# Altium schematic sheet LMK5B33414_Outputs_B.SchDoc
size C; Date: Not shown in title block; ApprovedBy: Not shown in title block; CheckedBy: Not shown in title block; Author: Not shown in title block; CompanyName: Not shown in title block; Engineer: Not shown in title block; Organization: Not shown in title block; Address1: Not shown in title block; Address2: Not shown in title block; Address3: Not shown in title block; Address4: Not shown in title block; DocumentNumber: 2; Revision: Use project parameter SCH_Rev; SheetNumber: 2; SheetTotal: 3; PageSetup: Record=PageOptions¦CenterHorizontal=True¦CenterVertical=True¦PrintScale=1.00¦XCorrection=1.00¦YCorrection=1.00¦PrintKind=0¦BorderSize=5000000¦LeftOffset=0¦BottomOffset=0¦Orientation=2¦PaperLength=1000¦PaperWidth=1000¦Scale=100¦PaperSource=15¦PrintQuality=600¦MediaType=1¦DitherType=10¦PaperKind=Letter¦PrintScaleMode=1
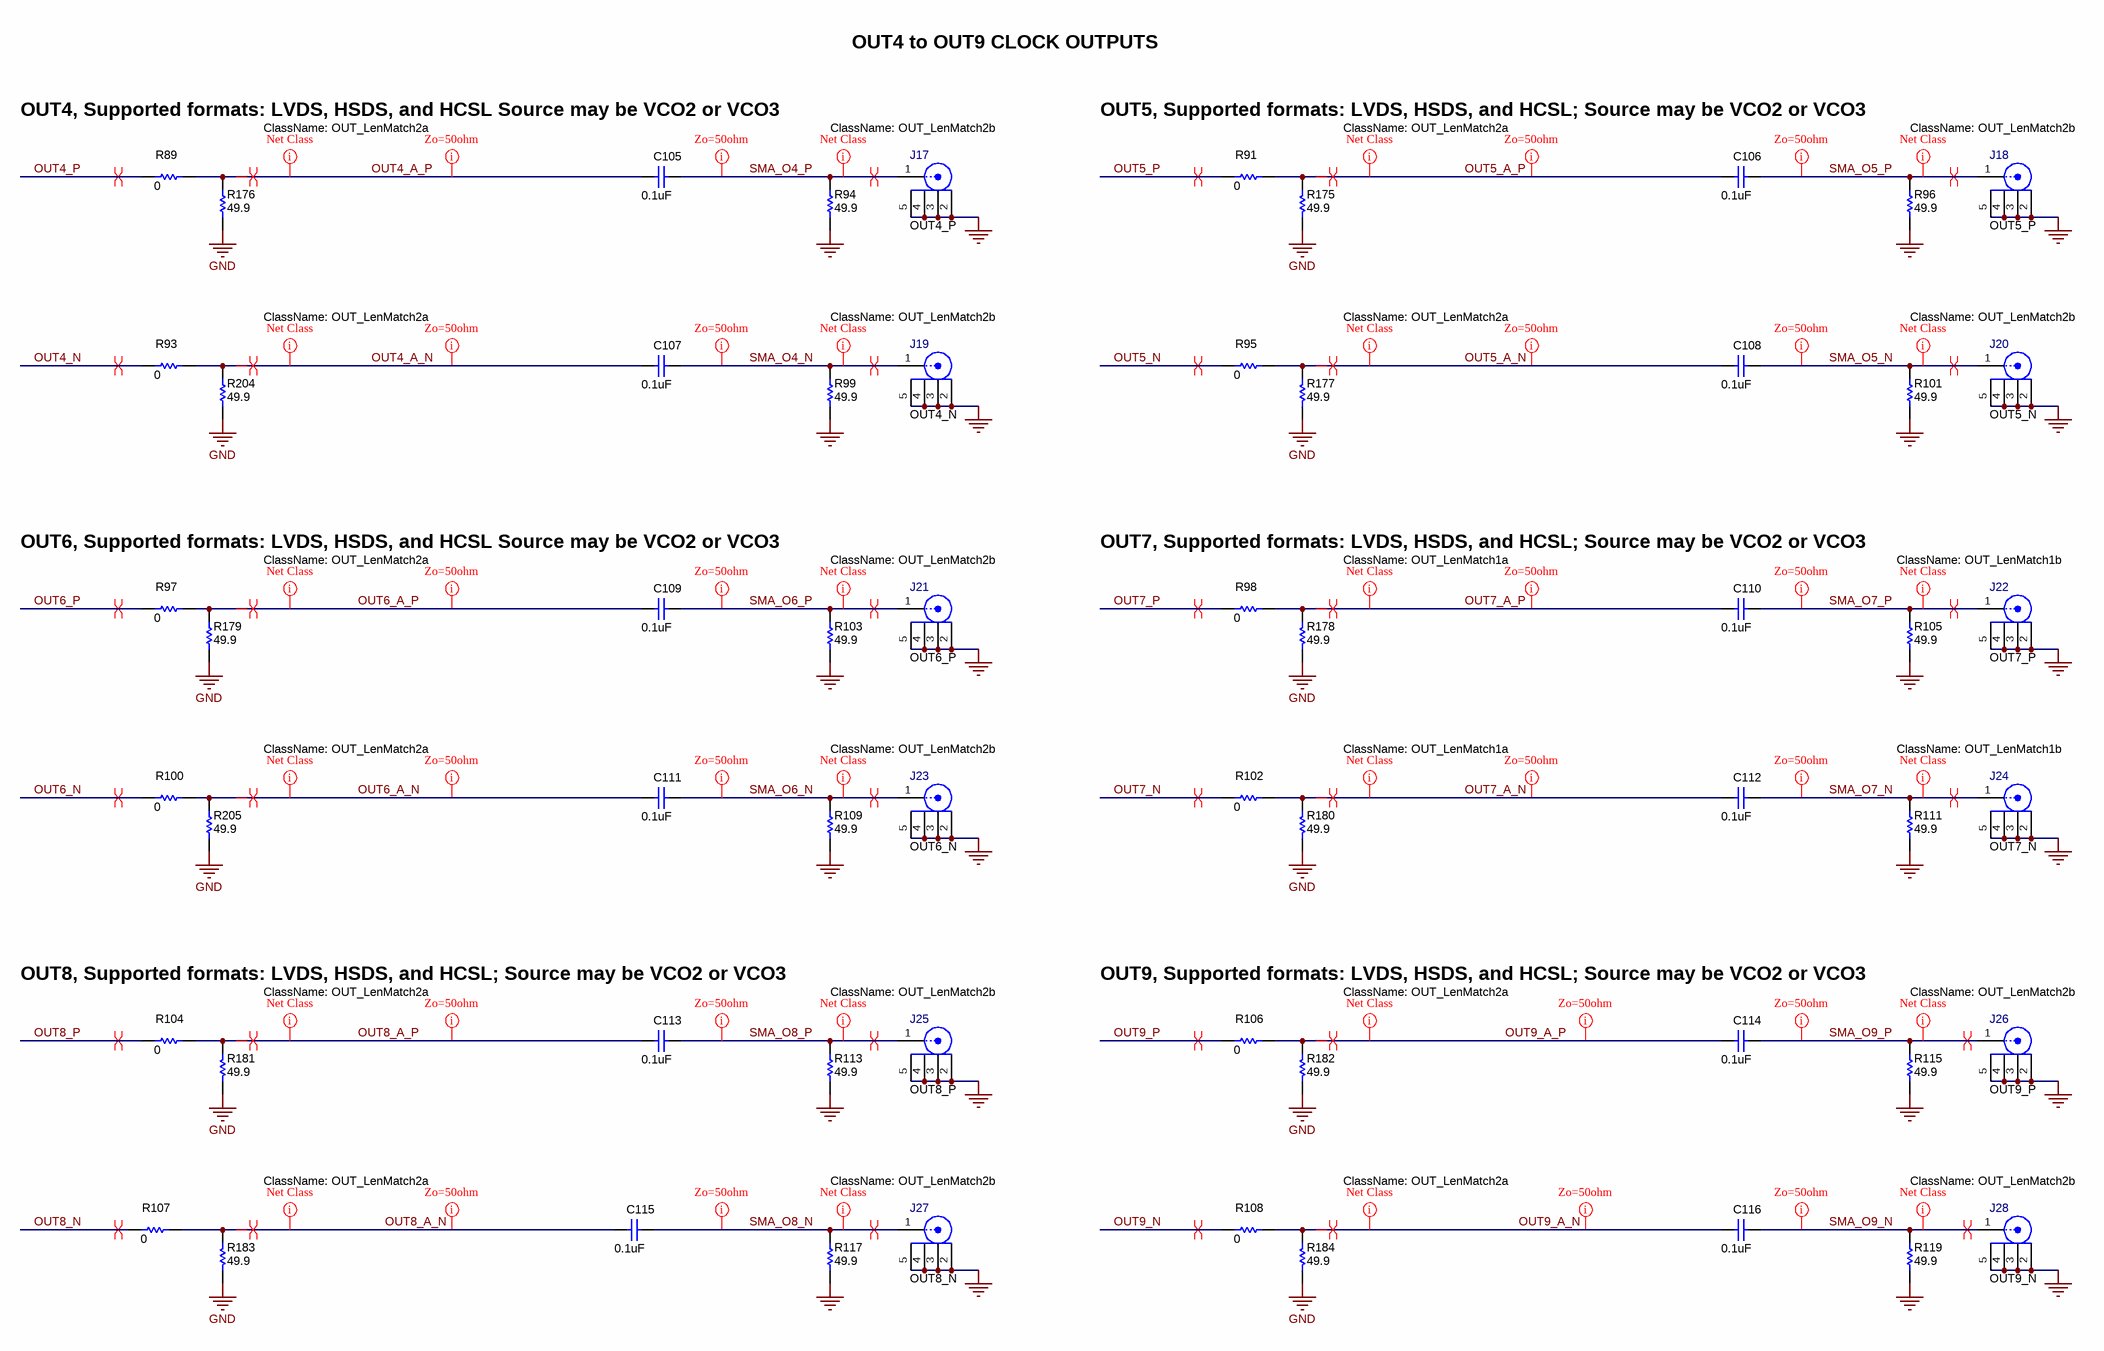
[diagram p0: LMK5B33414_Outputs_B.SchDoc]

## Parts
C105  ValueDisplayed: 0.1uF  [0402L]  (hidden comment: GRM155R71E104KE14D)
C106  ValueDisplayed: 0.1uF  [0402L]  (hidden comment: GRM155R71E104KE14D)
C107  ValueDisplayed: 0.1uF  [0402L]  (hidden comment: GRM155R71E104KE14D)
C108  ValueDisplayed: 0.1uF  [0402L]  (hidden comment: GRM155R71E104KE14D)
C109  ValueDisplayed: 0.1uF  [0402L]  (hidden comment: GRM155R71E104KE14D)
C110  ValueDisplayed: 0.1uF  [0402L]  (hidden comment: GRM155R71E104KE14D)
C111  ValueDisplayed: 0.1uF  [0402L]  (hidden comment: GRM155R71E104KE14D)
C112  ValueDisplayed: 0.1uF  [0402L]  (hidden comment: GRM155R71E104KE14D)
C113  ValueDisplayed: 0.1uF  [0402L]  (hidden comment: GRM155R71E104KE14D)
C114  ValueDisplayed: 0.1uF  [0402L]  (hidden comment: GRM155R71E104KE14D)
C115  ValueDisplayed: 0.1uF  [0402L]  (hidden comment: GRM155R71E104KE14D)
C116  ValueDisplayed: 0.1uF  [0402L]  (hidden comment: GRM155R71E104KE14D)
J17  OUT4_P  [FP-CON-SMA-EDGE-S_CONN_JACK-MFG]
J18  OUT5_P  [FP-CON-SMA-EDGE-S_CONN_JACK-MFG]
J19  OUT4_N  [FP-CON-SMA-EDGE-S_CONN_JACK-MFG]
J20  OUT5_N  [FP-CON-SMA-EDGE-S_CONN_JACK-MFG]
J21  OUT6_P  [FP-CON-SMA-EDGE-S_CONN_JACK-MFG]
J22  OUT7_P  [FP-CON-SMA-EDGE-S_CONN_JACK-MFG]
J23  OUT6_N  [FP-CON-SMA-EDGE-S_CONN_JACK-MFG]
J24  OUT7_N  [FP-CON-SMA-EDGE-S_CONN_JACK-MFG]
J25  OUT8_P  [FP-CON-SMA-EDGE-S_CONN_JACK-MFG]
J26  OUT9_P  [FP-CON-SMA-EDGE-S_CONN_JACK-MFG]
J27  OUT8_N  [FP-CON-SMA-EDGE-S_CONN_JACK-MFG]
J28  OUT9_N  [FP-CON-SMA-EDGE-S_CONN_JACK-MFG]
R89  ValueDisplayed: 0  [0402L]  (hidden comment: RK73Z1ETTP)
R91  ValueDisplayed: 0  [0402L]  (hidden comment: RK73Z1ETTP)
R93  ValueDisplayed: 0  [0402L]  (hidden comment: RK73Z1ETTP)
R94  ValueDisplayed: 49.9  [0402S]  (hidden comment: ERJ-2RKF49R9X)
R95  ValueDisplayed: 0  [0402L]  (hidden comment: RK73Z1ETTP)
R96  ValueDisplayed: 49.9  [0402S]  (hidden comment: ERJ-2RKF49R9X)
R97  ValueDisplayed: 0  [0402L]  (hidden comment: RK73Z1ETTP)
R98  ValueDisplayed: 0  [0402L]  (hidden comment: RK73Z1ETTP)
R99  ValueDisplayed: 49.9  [0402S]  (hidden comment: ERJ-2RKF49R9X)
R100  ValueDisplayed: 0  [0402L]  (hidden comment: RK73Z1ETTP)
R101  ValueDisplayed: 49.9  [0402S]  (hidden comment: ERJ-2RKF49R9X)
R102  ValueDisplayed: 0  [0402L]  (hidden comment: RK73Z1ETTP)
R103  ValueDisplayed: 49.9  [0402S]  (hidden comment: ERJ-2RKF49R9X)
R104  ValueDisplayed: 0  [0402L]  (hidden comment: RK73Z1ETTP)
R105  ValueDisplayed: 49.9  [0402S]  (hidden comment: ERJ-2RKF49R9X)
R106  ValueDisplayed: 0  [0402L]  (hidden comment: RK73Z1ETTP)
R107  ValueDisplayed: 0  [0402L]  (hidden comment: RK73Z1ETTP)
R108  ValueDisplayed: 0  [0402L]  (hidden comment: RK73Z1ETTP)
R109  ValueDisplayed: 49.9  [0402S]  (hidden comment: ERJ-2RKF49R9X)
R111  ValueDisplayed: 49.9  [0402S]  (hidden comment: ERJ-2RKF49R9X)
R113  ValueDisplayed: 49.9  [0402S]  (hidden comment: ERJ-2RKF49R9X)
R115  ValueDisplayed: 49.9  [0402S]  (hidden comment: ERJ-2RKF49R9X)
R117  ValueDisplayed: 49.9  [0402S]  (hidden comment: ERJ-2RKF49R9X)
R119  ValueDisplayed: 49.9  [0402S]  (hidden comment: ERJ-2RKF49R9X)
R175  ValueDisplayed: 49.9  [0402S]  (hidden comment: ERJ-2RKF49R9X)
R176  ValueDisplayed: 49.9  [0402S]  (hidden comment: ERJ-2RKF49R9X)
R177  ValueDisplayed: 49.9  [0402S]  (hidden comment: ERJ-2RKF49R9X)
R178  ValueDisplayed: 49.9  [0402S]  (hidden comment: ERJ-2RKF49R9X)
R179  ValueDisplayed: 49.9  [0402S]  (hidden comment: ERJ-2RKF49R9X)
R180  ValueDisplayed: 49.9  [0402S]  (hidden comment: ERJ-2RKF49R9X)
R181  ValueDisplayed: 49.9  [0402S]  (hidden comment: ERJ-2RKF49R9X)
R182  ValueDisplayed: 49.9  [0402S]  (hidden comment: ERJ-2RKF49R9X)
R183  ValueDisplayed: 49.9  [0402S]  (hidden comment: ERJ-2RKF49R9X)
R184  ValueDisplayed: 49.9  [0402S]  (hidden comment: ERJ-2RKF49R9X)
R204  ValueDisplayed: 49.9  [0402S]  (hidden comment: ERJ-2RKF49R9X)
R205  ValueDisplayed: 49.9  [0402S]  (hidden comment: ERJ-2RKF49R9X)

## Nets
GND: J17.2 J17.3 J17.4 J17.5 J18.2 J18.3 J18.4 J18.5 J19.2 J19.3 J19.4 J19.5 J20.2 J20.3 J20.4 J20.5 J21.2 J21.3 J21.4 J21.5 J22.2 J22.3 J22.4 J22.5 J23.2 J23.3 J23.4 J23.5 J24.2 J24.3 J24.4 J24.5 J25.2 J25.3 J25.4 J25.5 J26.2 J26.3 J26.4 J26.5 J27.2 J27.3 J27.4 J27.5 J28.2 J28.3 J28.4 J28.5 R94.1 R96.1 R99.1 R101.1 R103.1 R105.1 R109.1 R111.1 R113.1 R115.1 R117.1 R119.1 R175.2 R176.2 R177.2 R178.2 R179.2 R180.2 R181.2 R182.2 R183.2 R184.2 R204.2 R205.2
OUT4_A_N: C107.2 R93.2 R204.1
OUT4_A_P: C105.2 R89.2 R176.1
OUT4_N: R93.1
OUT4_P: R89.1
OUT5_A_N: C108.2 R95.2 R177.1
OUT5_A_P: C106.2 R91.2 R175.1
OUT5_N: R95.1
OUT5_P: R91.1
OUT6_A_N: C111.2 R100.2 R205.1
OUT6_A_P: C109.2 R97.2 R179.1
OUT6_N: R100.1
OUT6_P: R97.1
OUT7_A_N: C112.2 R102.2 R180.1
OUT7_A_P: C110.2 R98.2 R178.1
OUT7_N: R102.1
OUT7_P: R98.1
OUT8_A_N: C115.2 R107.2 R183.1
OUT8_A_P: C113.2 R104.2 R181.1
OUT8_N: R107.1
OUT8_P: R104.1
OUT9_A_N: C116.2 R108.2 R184.1
OUT9_A_P: C114.2 R106.2 R182.1
OUT9_N: R108.1
OUT9_P: R106.1
SMA_O4_N: C107.1 J19.1 R99.2
SMA_O4_P: C105.1 J17.1 R94.2
SMA_O5_N: C108.1 J20.1 R101.2
SMA_O5_P: C106.1 J18.1 R96.2
SMA_O6_N: C111.1 J23.1 R109.2
SMA_O6_P: C109.1 J21.1 R103.2
SMA_O7_N: C112.1 J24.1 R111.2
SMA_O7_P: C110.1 J22.1 R105.2
SMA_O8_N: C115.1 J27.1 R117.2
SMA_O8_P: C113.1 J25.1 R113.2
SMA_O9_N: C116.1 J28.1 R119.2
SMA_O9_P: C114.1 J26.1 R115.2

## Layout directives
rule Impedance Constraint [Min = 45.00    Max = 55.00    ]: OUT4_A_N, OUT4_A_P, OUT5_A_N, OUT5_A_P, OUT6_A_N, OUT6_A_P, OUT7_A_N, OUT7_A_P, OUT8_A_N, OUT8_A_P, OUT9_A_N, OUT9_A_P, SMA_O4_N, SMA_O4_P, SMA_O5_N, SMA_O5_P, SMA_O6_N, SMA_O6_P, SMA_O7_N, SMA_O7_P, SMA_O8_N, SMA_O8_P, SMA_O9_N, SMA_O9_P
differential pair: OUT4_A_N, OUT4_A_P, OUT4_N, OUT4_P, OUT5_A_N, OUT5_A_P, OUT5_N, OUT5_P, OUT6_A_N, OUT6_A_P, OUT6_N, OUT6_P, OUT7_A_N, OUT7_A_P, OUT7_N, OUT7_P, OUT8_A_N, OUT8_A_P, OUT8_N, OUT8_P, OUT9_A_N, OUT9_A_P, OUT9_N, OUT9_P, SMA_O4_N, SMA_O4_P, SMA_O5_N, SMA_O5_P, SMA_O6_N, SMA_O6_P, SMA_O7_N, SMA_O7_P, SMA_O8_N, SMA_O8_P, SMA_O9_N, SMA_O9_P
net class OUT_LenMatch2a: OUT4_A_N, OUT4_A_P, OUT5_A_N, OUT5_A_P, OUT6_A_N, OUT6_A_P, OUT8_A_N, OUT8_A_P, OUT9_A_N, OUT9_A_P
net class OUT_LenMatch1a: OUT7_A_N, OUT7_A_P
net class OUT_LenMatch2b: SMA_O4_N, SMA_O4_P, SMA_O5_N, SMA_O5_P, SMA_O6_N, SMA_O6_P, SMA_O8_N, SMA_O8_P, SMA_O9_N, SMA_O9_P
net class OUT_LenMatch1b: SMA_O7_N, SMA_O7_P

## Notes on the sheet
- OUT4 to OUT9 CLOCK OUTPUTS
- OUT4, Supported formats: LVDS, HSDS, and HCSL Source may be VCO2 or VCO3
- OUT5, Supported formats: LVDS, HSDS, and HCSL; Source may be VCO2 or VCO3
- OUT6, Supported formats: LVDS, HSDS, and HCSL Source may be VCO2 or VCO3
- OUT7, Supported formats: LVDS, HSDS, and HCSL; Source may be VCO2 or VCO3
- OUT8, Supported formats: LVDS, HSDS, and HCSL; Source may be VCO2 or VCO3
- OUT9, Supported formats: LVDS, HSDS, and HCSL; Source may be VCO2 or VCO3

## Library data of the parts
C105-C116 = CMP-0006659-2: CAP, CERM, 0.1 uF, 25 V, +/- 10%, X7R, 0402; Manufacturer: MuRata; TaMin_C: -55°C; Polarized: N; SizeAreaWB_mm2: 3; Value1: Unknown; U/M: EA; Value: 0.1uF; TaMax_C: 125°C; SizeZ_mm: 0.6; SizeX_mm: 1; SizeY_mm: 0.5; Cap_Case: 0402; Value2: 25V; CompType: Capacitor; Cap_F: 100nF; AEC Category: Q200
J17-J28 = CMP-0088000-4: CONN SMA JACK STR EDGE MNT; Manufacturer: RF Solutions Ltd.; PartNumber: CON-SMA-EDGE-S; ContactFinish: Gold; Shrouded: true
R89 R91 R93 R95 R97 R98 R100 R102 R104 R106-R108 = CMP-0027007-2: RES, 0, 5%, 0.063 W, AEC-Q200 Grade 0, 0402; Manufacturer: KOA Speer; Power_W: 63mW; TempCo: ppm/C; Value_Code: 0000; U/M: EA; Value: 0; EIA_Code: E24; SizeX_mm: 1; SizeY_mm: 0.5; SizeZ_mm: 0.6; Value2: 0.063W; CompType: Resistor; AEC Qualified: Y; AEC Category: Q200
R94 R99 R101 R103 R105 R111 R113 R115 R117 R119 = CMP-0026703-1: RES, 49.9, 1%, 0.1 W, AEC-Q200 Grade 0, 0402; Manufacturer: Panasonic; Value: 49.9; Value_Code: 49R9; Power_W: 100mW; Value2: 0.1W; VDC_V: 50V; TempCo: 100 ppm/C; EIA_Code: E96; SizeArea_mm2: 0.5; SizeX_mm: 1; SizeZ_mm: 0.6; AEC Category: Q200; AEC Qualified: Y; AEC Grade: 0; U/M: EA
R96 R109 = CMP-0026703-1: RES, 49.9, 1%, 0.1 W, AEC-Q200 Grade 0, 0402; Manufacturer: Panasonic; CompType: Resistor; Value: 49.9; Value_Code: 49R9; Power_W: 100mW; Value2: 0.1W; VDC_V: 50V; TempCo: 100 ppm/C; EIA_Code: E96; SizeArea_mm2: 0.5; SizeX_mm: 1; SizeZ_mm: 0.6; AEC Category: Q200; AEC Qualified: Y; AEC Grade: 0; U/M: EA
R175-R184 R204 R205 = CMP-0026703-1: RES, 49.9, 1%, 0.1 W, AEC-Q200 Grade 0, 0402; Manufacturer: Panasonic; Power_W: 100mW; TempCo: 100 ppm/C; Value_Code: 49R9; Value: 49.9; EIA_Code: E96; SizeX_mm: 1; SizeY_mm: 0.5; SizeZ_mm: 0.6; Value2: 0.1W; AEC Qualified: Y; VDC_V: 50V; AEC Category: Q200; AEC Grade: 0; U/M: EA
